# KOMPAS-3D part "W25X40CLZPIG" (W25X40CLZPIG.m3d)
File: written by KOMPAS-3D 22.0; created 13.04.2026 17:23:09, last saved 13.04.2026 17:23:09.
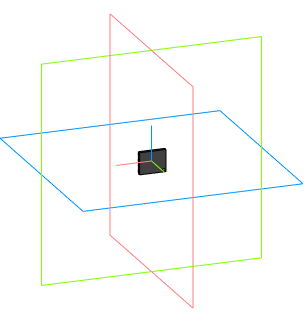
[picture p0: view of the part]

Document properties: Автор: Andrey; Полное имя файла: C:\Users\User1\Documents\W25X40CLZPIG.m3d

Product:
- Part/product: W25X40CLZPIG

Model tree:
1. Операция без истории:1
2. Операция без истории:2
3. Операция без истории:3
4. Операция без истории:4
5. Операция без истории:5
6. Операция без истории:6
7. Операция без истории:7
8. Операция без истории:8
9. Операция без истории:9
10. Операция без истории:10
11. Операция без истории:11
